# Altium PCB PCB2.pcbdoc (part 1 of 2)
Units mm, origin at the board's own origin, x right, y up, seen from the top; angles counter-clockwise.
Board outline 201.42 x 135 mm, 2 copper layers (Top Layer, Bottom Layer); 117 components, 69 nets, 446 pads, 480 vias.
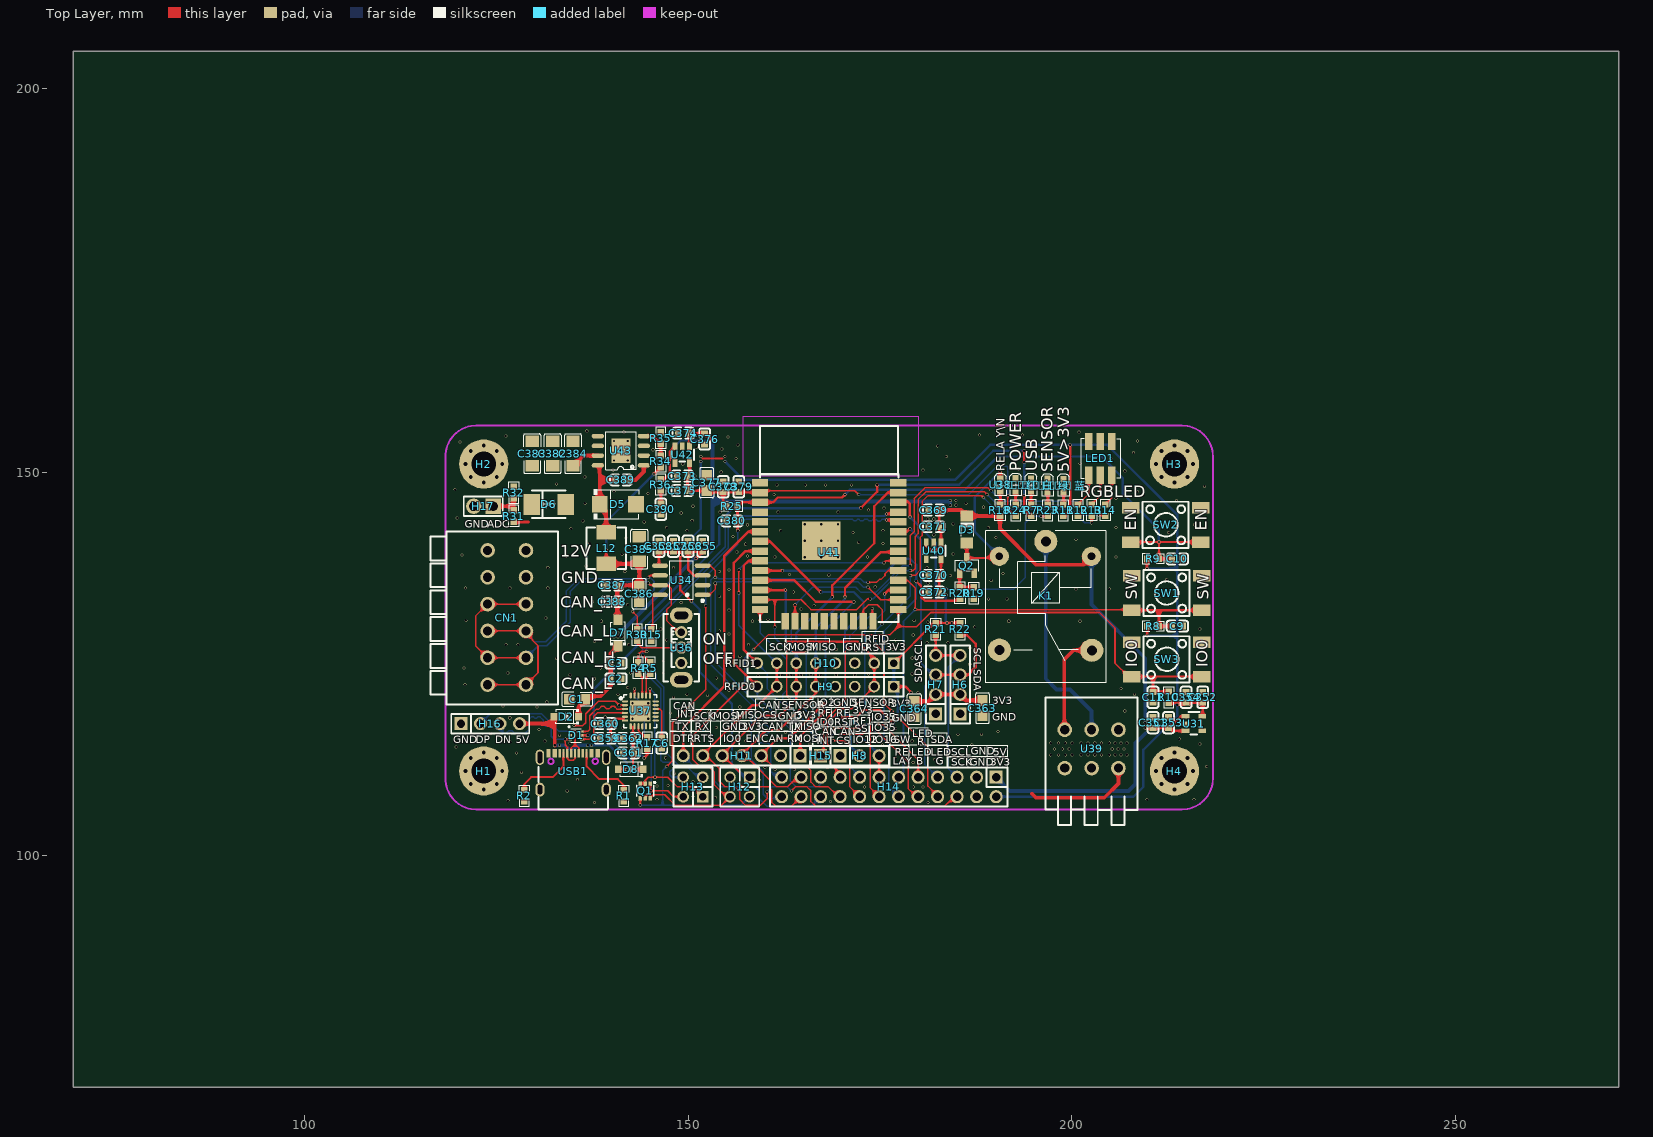
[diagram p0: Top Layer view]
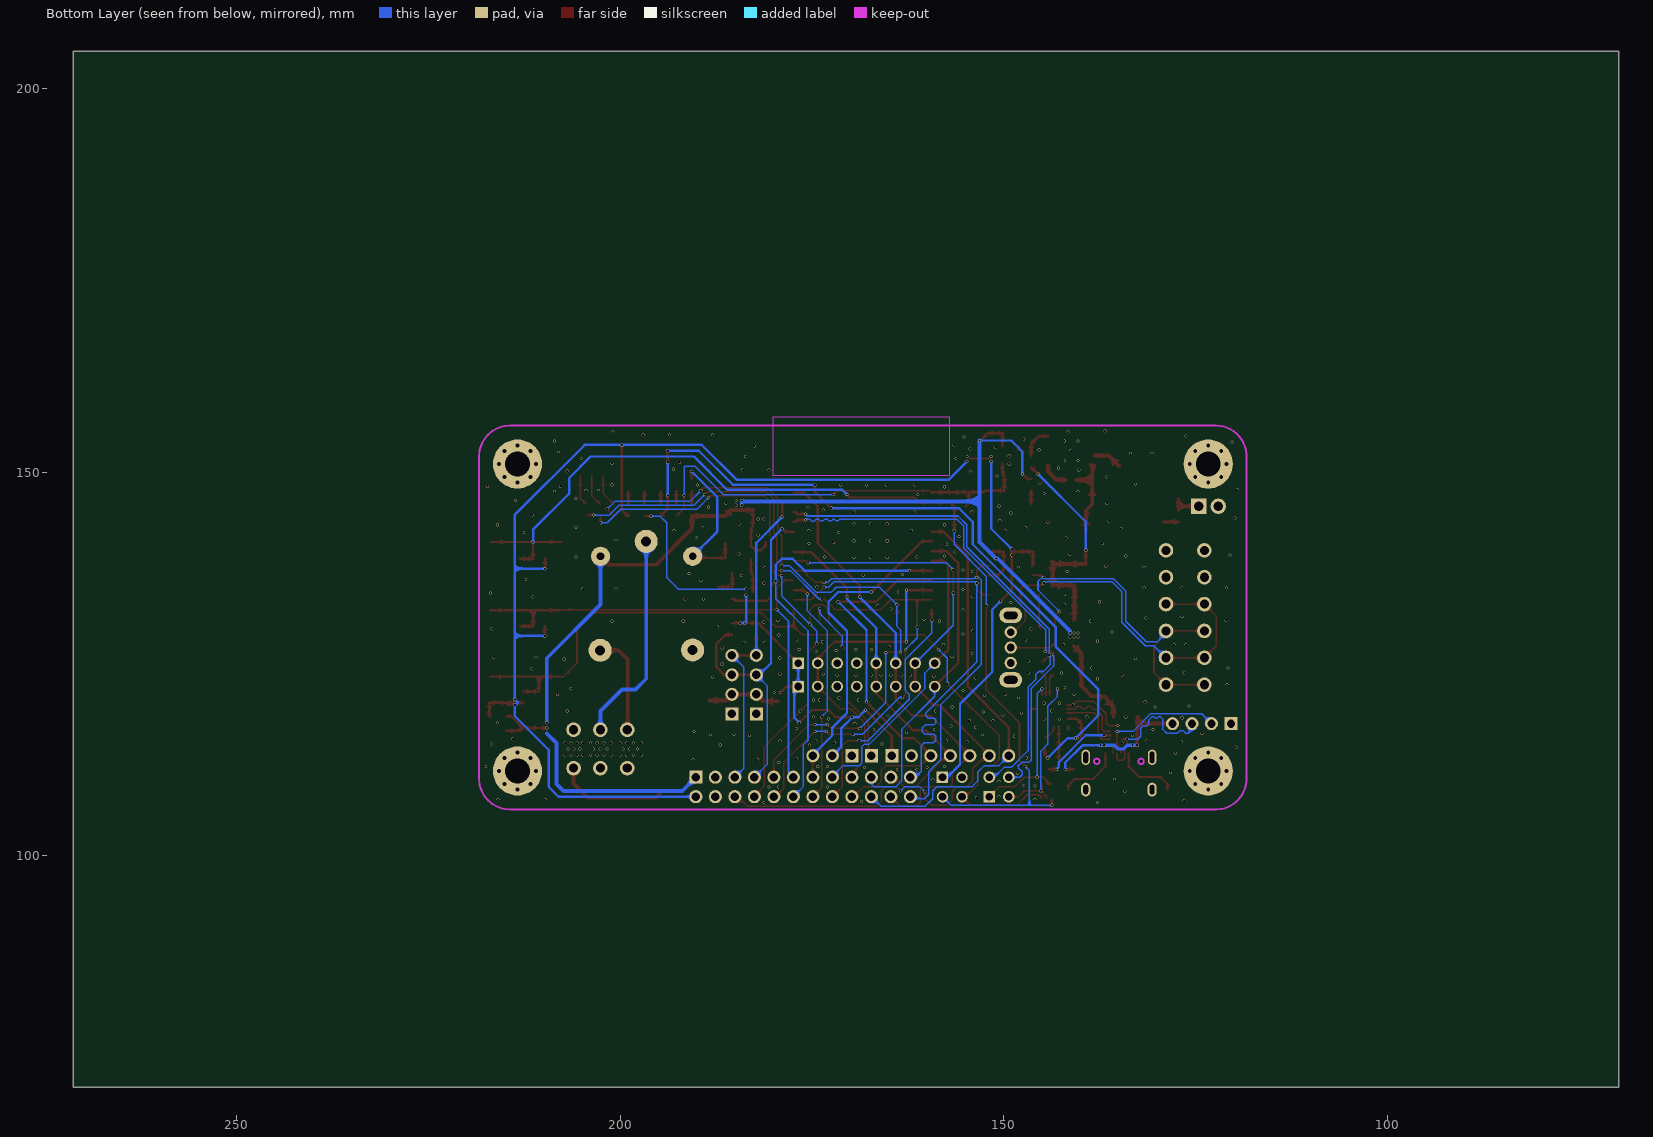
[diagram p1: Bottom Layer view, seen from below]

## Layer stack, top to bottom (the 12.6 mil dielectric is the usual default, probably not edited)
Top Layer: signal copper (thickness not stored)
Dielectric: dielectric 0.32, FR-4, Dk 4.8
Bottom Layer: signal copper (thickness not stored)

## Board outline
271.272,69.85 69.85,69.85 69.85,204.851 271.272,204.851

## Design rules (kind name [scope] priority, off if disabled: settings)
Clearance copperThickness1oz [All] p1: gap=0.178 ignorepadtopadclearanceinfootprint=FALSE except(0.099: Track-Track Track-SMDPad SMDPad-SMDPad Track-THPad SMDPad-THPad THPad-THPad Track-Via SMDPad-Via THPad-Via Via-Via Track-Fill SMDPad-Fill THPad-Fill Via-Fill Fill-Fill Track-Region SMDPad-Region THPad-Region Via-Region Fill-Region Region-Region Track-Poly SMDPad-Poly THPad-Poly Via-Poly Fill-Poly Region-Poly Poly-Poly Track-Text SMDPad-Text THPad-Text Via-Text Fill-Text Region-Text Poly-Text Text-Text Track-Hole SMDPad-Hole THPad-Hole Via-Hole Fill-Hole Region-Hole Poly-Hole Text-Hole; 0.254: SMDPad-Sheet; 0.3: Track-Sheet THPad-Sheet Via-Sheet Fill-Sheet Region-Sheet Poly-Sheet Text-Sheet Sheet-Hole)
Clearance copperThickness2oz [All] p1: gap=0.178 ignorepadtopadclearanceinfootprint=FALSE except(0.152: Track-SMDPad SMDPad-SMDPad Track-THPad SMDPad-THPad THPad-THPad Track-Via SMDPad-Via THPad-Via Via-Via Track-Fill SMDPad-Fill THPad-Fill Via-Fill Fill-Fill SMDPad-Region THPad-Region Via-Region Fill-Region Region-Region Track-Poly SMDPad-Poly THPad-Poly Via-Poly Fill-Poly Poly-Poly Track-Text SMDPad-Text THPad-Text Via-Text Fill-Text Region-Text Poly-Text Text-Text Track-Hole SMDPad-Hole THPad-Hole Via-Hole Fill-Hole Region-Hole Poly-Hole Text-Hole; 0.203: Track-Track; 0.3: Track-Region Region-Poly Track-Sheet SMDPad-Sheet THPad-Sheet Via-Sheet Fill-Sheet Region-Sheet Poly-Sheet Text-Sheet Sheet-Hole)
Clearance copperThicknessInner0.5oz [All] p1: gap=0.178 ignorepadtopadclearanceinfootprint=FALSE except(0.089: Track-Track; 0.152: Track-SMDPad SMDPad-SMDPad Track-THPad SMDPad-THPad THPad-THPad Track-Via SMDPad-Via THPad-Via Via-Via Track-Fill SMDPad-Fill THPad-Fill Via-Fill Fill-Fill SMDPad-Region THPad-Region Via-Region Fill-Region Region-Region Track-Poly SMDPad-Poly THPad-Poly Via-Poly Fill-Poly Poly-Poly Track-Text SMDPad-Text THPad-Text Via-Text Fill-Text Region-Text Poly-Text Text-Text Track-Hole SMDPad-Hole THPad-Hole Via-Hole Fill-Hole Region-Hole Poly-Hole Text-Hole; 0.3: Track-Region Region-Poly Track-Sheet SMDPad-Sheet THPad-Sheet Via-Sheet Fill-Sheet Region-Sheet Poly-Sheet Text-Sheet Sheet-Hole)
DiffPairsRouting differentialPair [All] p1: maxuncoupledlength=10 maxlimit=7.874 mostfreqgap=7.874 toplayer_minwidth=5 toplayer_prefwidth=10 toplayer_maxwidth=100 bottomlayer_minwidth=5 bottomlayer_prefwidth=10 bottomlayer_maxwidth=100
PasteMaskExpansion pasteMaskExpansion [All] p1:
PlaneConnect innerPlane [All] p1: planeconnectstyle=Relief reliefexpansion=0.508 reliefentries=4 reliefconductorwidth=0.254 reliefairgap=0.254
PolygonConnect copperRegionvusb [All] p1: connectstyle=Direct reliefentries=4 reliefconductorwidth=10 polygonreliefangle="90 Angle" airgapwidth=10
PolygonConnect copperRegion0p2 [All] p1: connectstyle=Direct reliefentries=4 reliefconductorwidth=10 polygonreliefangle="90 Angle" airgapwidth=10
PolygonConnect copperRegion1 [All] p1: connectstyle=Direct reliefentries=4 reliefconductorwidth=10 polygonreliefangle="90 Angle" airgapwidth=10
RoutingVias viaSize [All] p1: viastyle="Through Hole" holewidth=11.811 minholewidth=11.811 maxholewidth=248.0314 width=15.748 minwidth=15.748 maxwidth=393.7008
SolderMaskExpansion solderMaskExpansion [All] p1: useseparateexpansions=TRUE expansion=2.0079 expansionbottom=2.0079
Width copperThickness1oz [All] p1: maxlimit=394 minlimit=4 preferedwidth=8
Width copperThickness0.5oz [All] p1: maxlimit=100 minlimit=4 preferedwidth=10
Width copperThickness2oz [All] p1: maxlimit=100 minlimit=8 preferedwidth=10

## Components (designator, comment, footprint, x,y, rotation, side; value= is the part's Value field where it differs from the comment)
C1 "CGA0805X5R226M350MT" C0805 135.509,120.396 r180 top
C2 "CL10A106MA8NRNC" C0603 140.589,123.063 r0 top
C3 "CGA0603X7R104K500JT" C0603 140.589,125.095 r0 top
C6 "CGA0603X5R475K250JT" C0603 146.558,114.681 r90 top
C9 "CGA0603X7R104K500JT" C0603 213.741,129.921 r0 top
C10 "CGA0603X7R104K500JT" C0603 213.741,138.684 r0 top
C11 "CGA0603X7R104K500JT" C0603 210.566,120.65 r270 top
C351 "CL10A106MA8NRNC" C0603 210.566,117.348 r270 top
C352 "CL10A106MA8NRNC" C0603 217.043,120.65 r270 top
C353 "CGA0603X7R104K500JT" C0603 212.598,117.348 r270 top
C354 "CGA0603X7R104K500JT" C0603 214.884,120.65 r270 top
C355 "CL10A106MA8NRNC" C0603 151.892,140.335 r270 top
C356 "CGA0603X7R104K500JT" C0603 149.987,140.335 r270 top
C357 "CL10A106MA8NRNC" C0603 148.082,140.335 r270 top
C358 "CGA0603X7R104K500JT" C0603 146.177,140.335 r270 top
C359 "CGA0603X7R104K500JT" C0603 139.192,115.316 r0 top
C360 "CGA0603X5R475K250JT" C0603 139.192,117.221 r0 top
C361 "CL10A106MA8NRNC" C0603 142.24,113.411 r0 top
C362 "CGA0603X7R104K500JT" C0603 142.24,115.316 r0 top
C363 "CGA0805X5R226M350MT" C0805 188.341,119.253 r270 top
C364 "CGA0805X5R226M350MT" C0805 179.451,119.126 r270 top
C369 "CL10A106MA8NRNC" C0603 181.991,145.034 r0 top
C370 "CL10A106MA8NRNC" C0603 181.991,136.525 r0 top
C371 "CGA0603X7R104K500JT" C0603 181.991,142.875 r0 top
C372 "CGA0603X7R104K500JT" C0603 181.991,134.366 r0 top
C373 "CL10A106MA8NRNC" C0603 149.225,149.479 r0 top
C374 "CGA0603X7R104K500JT" C0603 149.352,155.067 r0 top
C375 "CGA0603X7R104K500JT" C0603 149.225,147.574 r0 top
C376 "CL10A106MA8NRNC" C0603 152.146,154.305 r90 top
C377 "CGA0805X5R226M350MT" C0805 152.4,148.59 r90 top
C378 "CL10A106MA8NRNC" C0603 154.559,148.082 r90 top
C379 "CGA0603X7R104K500JT" C0603 156.591,148.082 r90 top
C380 "CGA0603X7R104K500JT" C0603 155.702,143.637 r180 top
C382 "HGC1206R5106K500NSPJ" C1206 132.334,152.4 r270 top
C383 "CGA1206X5R226M350NT" C1206 129.667,152.4 r270 top
C384 "CL31B104KBCNNNC" C1206 135.001,152.4 r270 top
C385 "HGC1206R5476M250NSPJ" C1206 143.637,139.954 r270 top
C386 "CGA0805X5R226M350MT" C0805 143.637,134.112 r90 top
C387 "CL10A106MA8NRNC" C0603 140.081,135.255 r0 top
C388 "CGA0603X7R104K500JT" C0603 140.081,133.096 r0 top
C389 "CGA0603X7R104K500JT" C0603 141.224,148.971 r0 top
C390 "CGA0603X5R475K250JT" C0603 146.431,145.161 r90 top
CN1 "New_Library_2601-1106" CONN-TH_2601-1106 126.364,131.045 r270 top
D1 "USBLC6-2P6_C2827693" SOT-666-6_L1.6-W1.2-P0.50-LS1.6-BL 135.382,115.697 r270 top
D2 "5819W" SOD-123_L2.7-W1.6-LS3.7-FD 134.112,118.11 r0 top
D3 "LL4148-GS08" SOD-80_L3.5-W1.5-RD 186.309,142.494 r270 top
D5 "SS54SMB" SMB_L4.6-W3.6-LS5.3-RD 140.843,145.796 r0 top
D6 "SMBJ28A" SMB_L4.6-W3.6-LS5.3-L-FD 131.826,145.796 r180 top
D7 "DSK34_C7502709" SOD-123FL_L2.7-W1.8-LS3.8-RD 140.843,129.032 r90 top
D8 "5819W" SOD-123_L2.7-W1.6-LS3.7-FD 142.494,111.252 r0 top
H1 "Mechanical_MountingHole_Pad" MountingHole:MountingHole_3.2mm_M3_Pad_Via 123.364,111.045 r0 top
H2 "Mechanical_MountingHole_Pad" MountingHole:MountingHole_3.2mm_M3_Pad_Via 123.364,151.045 r0 top
H3 "Mechanical_MountingHole_Pad" MountingHole:MountingHole_3.2mm_M3_Pad_Via 213.364,151.045 r0 top
H4 "Mechanical_MountingHole_Pad" MountingHole:MountingHole_3.2mm_M3_Pad_Via 213.364,111.045 r0 top
H6 "PZ254V-11-04P" HDR-TH_4P-P2.54-V-M 185.42,122.301 r90 top
H7 "PZ254V-11-04P" HDR-TH_4P-P2.54-V-M 182.245,122.301 r90 top
H8 "PZ254V-11-03P" HDR-TH_3P-P2.54-V-M 172.339,113.03 r0 top
H9 "PZ254V-11-08P" HDR-TH_8P-P2.54-V-M 167.894,122.047 r180 top
H10 "PZ254V-11-08P" HDR-TH_8P-P2.54-V-M 167.894,125.095 r180 top
H11 "HX PZ2.54-1x7P ZZ" HDR-TH_7P-P2.54-V-M 156.972,113.03 r180 top
H12 "HX PZ2.54-2x2P ZZ" HDR-TH_HX-PZ2.54-2X2P-ZZ 156.718,108.966 r180 top
H13 "HX PZ2.54-2x2P ZZ" HDR-TH_HX-PZ2.54-2X2P-ZZ 150.622,108.966 r90 top
H14 "PZ254V-12-24P" HDR-TH_24P-P2.54-V-M-R2-C12-S2.54 176.149,108.966 r180 top
H15 "PZ254V-11-01P" HDR-TH_1P-P2.54-V-M 167.259,113.03 r0 top
H16 "PZ254V-11-04P" HDR-TH_4P-P2.54-V-M 124.206,117.221 r0 top
H17 "PZ254V-11-02P" HDR-TH_2P-P2.54-V-M 123.317,145.542 r180 top
K1 "Relay_SANYOU_SRD_Form_C" Relay_THT:Relay_SPDT_SANYOU_SRD_Series_Form_C 196.596,140.97 r270 top
L12 "FXL0530-100-M" IND-SMD_L5.4-W5.2_FXL0530 139.319,140.081 r270 top
LED1 "TC5050RGBF08-3CJH-AF53A" LED-SMD_6P-L5.0-W5.0-TL_TC5050RGBF08 203.708,151.765 r90 top
LED白 "NCD0603W1" LED0603-RD 194.691,148.209 r270 top
LED红 "SZYY0603R" LED0603-R-RD 192.659,148.336 r270 top
LED绿 "XL-1608PGC-06" LED0603-RD_GREEN 196.85,148.209 r270 top
LED蓝 "SZYY0603B" LED0603-R-RD_BLUE 198.882,148.209 r270 top
Q1 "UMH3N" SC-70-6_L2.2-W1.3-P0.65-LS2.1-BR 144.399,108.458 r90 top
Q2 "BC817_C916383" SOT-23-3_L2.9-W1.3-P1.90-LS2.4-BR 186.309,137.795 r270 top
R1 "0603WAF5101T5E" R0603 141.605,107.823 r270 top
R2 "0603WAF5101T5E" R0603 128.651,107.823 r270 top
R4 "0603WAF220JT5E" R0603 143.51,124.46 r90 top
R5 "0603WAF220JT5E" R0603 145.034,124.46 r90 top
R7 "0603WAF1002T5E" R0603 194.691,145.034 r90 top
R8 "0603WAF1002T5E" R0603 210.566,129.921 r180 top
R9 "0603WAF1002T5E" R0603 210.566,138.684 r180 top
R10 "0603WAF1002T5E" R0603 212.598,120.65 r270 top
R11 "0603WAF1002T5E" R0603 198.882,145.034 r270 top
R12 "0603WAF1001T5E" R0603 200.787,145.034 r90 top
R13 "0603WAF1001T5E" R0603 202.565,145.034 r90 top
R14 "0603WAF1001T5E" R0603 204.343,145.034 r90 top
R15 "0603WAF0000T5E" R0603 145.161,128.778 r270 top
R17 "0603WAF4701T5E" R0603 144.653,114.681 r90 top
R18 "0603WAF1002T5E" R0603 190.627,145.034 r90 top
R19 "0603WAF1002T5E" R0603 187.198,134.239 r270 top
R20 "0603WAF1001T5E" R0603 185.42,134.239 r90 top
R21 "0603WAF4701T5E" R0603 182.245,129.54 r270 top
R22 "0603WAF4701T5E" R0603 185.42,129.54 r270 top
R23 "0603WAF1002T5E" R0603 196.85,145.034 r270 top
R24 "0603WAF1002T5E" R0603 192.659,145.034 r270 top
R25 "0603WAF1002T5E" R0603 155.702,145.542 r0 top
R30 "0603WAF1200T5E" R0603 143.383,128.778 r90 top
R31 "FRC0603F8202TS" R0603 127.254,144.272 r90 top
R32 "0603WAF1002T5E" R0603 127.254,147.32 r270 top
R34 "0603WAF1003T5E" R0603 146.431,151.384 r90 top
R35 "0603WAF3132T5E" R0603 146.431,154.432 r90 top
R36 "FRC0603F4703TS" R0603 146.431,148.336 r90 top
SW1 "KH-6X6X5H-STM" SW-SMD_4P-L6.0-W6.0-P4.50-LS9.0_H5.0 212.344,134.239 r0 top
SW2 "KH-6X6X5H-STM" SW-SMD_4P-L6.0-W6.0-P4.50-LS9.0_H5.0 212.217,143.129 r0 top
SW3 "KH-6X6X5H-STM" SW-SMD_4P-L6.0-W6.0-P4.50-LS9.0_H5.0 212.344,125.603 r0 top
U31 "ME6211C30M5G-N" SOT-23-5_L2.9-W1.6-P0.95-LS2.8-BL 215.9,117.221 r270 top
U34 "TJA1051T/3/1J" SOIC-8_L4.9-W3.9-P1.27-LS6.0-BL 149.098,135.89 r90 top
U36 "HX SS12D07VG5" SW-TH_SS12D07VG3 149.098,127.127 r270 top
U37 "CP2104-F03-GMR" QFN-24_L4.0-W4.0-P0.50-BL-EP2.7 143.764,118.872 r270 top
U38 "MHT192WDT-GOLD" LED0603-RD-YELLOW 190.627,148.209 r270 top
U39 "2601-1103" CONN-TH_6P-P3.50_2601-1103 202.565,113.919 r0 top
U40 "ME6211C30M5G-N" SOT-23-5_L2.9-W1.6-P0.95-LS2.8-BL 181.991,139.73 r180 top
U41 "ESP32-WROOM-32D-N4" WIFIM-SMD_39P-L25.5-W18.0-P1.27-BL 168.364,139.573 r270 top
U42 "ME6211C30M5G-N" SOT-23-5_L2.9-W1.6-P0.95-LS2.8-BL 149.225,152.273 r180 top
U43 "TPS5450MDDAREP" POWERPAD-SO-8_L4.9-W3.9-P1.27-LS6.0-BL-EP 141.224,152.781 r90 top
USB1 "TYPE-C 16PIN 2MD(073)" USB-C-SMD_TYPE-C-6PIN-2MD-073 135.001,110.998 r0 top

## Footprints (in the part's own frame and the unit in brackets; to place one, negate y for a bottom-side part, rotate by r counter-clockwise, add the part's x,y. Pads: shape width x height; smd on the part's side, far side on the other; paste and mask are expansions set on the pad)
C0603 [mm]
  rect 0.8x0.9 smd: 1(-0.7,0) 2(0.7,0)
  silkscreen extent -1.39,-0.71 1.39,0.71
C0805 [mm]
  rect 1.41x1.35 smd: 1(-1,0) 2(1,0)
  silkscreen extent -1.96,-0.9 1.96,0.9
C1206 [mm]
  rect 1.485x1.728 smd: 1(-1.593,0) 2(1.593,0)
  silkscreen extent -2.56,-1.09 2.56,1.09
CONN-TH_6P-P3.50_2601-1103 [mm]
  round 1.9 hole 1.2: 1(-3.5,2.5) 2(-3.5,-2.5) 3(0,2.5) 4(0,-2.5) 5(3.5,2.5) 6(3.5,-2.5)
  silkscreen extent -6,-9.9 6,6.7
CONN-TH_2601-1106 [mm]
  round 1.9 hole 1.2: 1(-8.75,-2.5) 1(-8.75,2.5) 2(-5.25,2.5) 2(-5.25,-2.5) 3(-1.75,2.5) 3(-1.75,-2.5) 4(1.75,2.5) 4(1.75,-2.5) 5(5.25,2.5) 5(5.25,-2.5) 6(8.75,-2.5) 6(8.75,2.5)
  silkscreen extent -11.19,-9.93 11.31,6.65
HDR-TH_1P-P2.54-V-M [mm]
  rect 1.7x1.7 hole 1.1: 1(0,0)
  silkscreen extent -1.27,-1.27 1.27,1.27
HDR-TH_2P-P2.54-V-M [mm]
  rect 2x2 hole 1.2: 1(-1.27,0)
  round 2 hole 1.2: 2(1.27,0)
  silkscreen extent -2.54,-1.27 2.54,1.27
HDR-TH_3P-P2.54-V-M [mm]
  rect 1.7x1.7 hole 1.1: 1(-2.54,0)
  round 1.7 hole 1.1: 2(0,0) 3(2.54,0)
  silkscreen extent -3.81,-1.25 3.81,1.25
HDR-TH_4P-P2.54-V-M [mm]
  rect 1.7x1.7 hole 1.1: 1(-3.81,0)
  round 1.7 hole 1.1: 2(-1.27,0) 3(1.27,0) 4(3.81,0)
  silkscreen extent -5.08,-1.27 5.08,1.27
HDR-TH_7P-P2.54-V-M [mm]
  rect 1.7x1.7 hole 1.1: 1(-7.62,0)
  round 1.7 hole 1.1: 2(-5.08,0) 3(-2.54,0) 4(0,0) 5(2.54,0) 6(5.08,0) 7(7.62,0)
  silkscreen extent -8.89,-1.25 8.89,1.25
HDR-TH_8P-P2.54-V-M [mm]
  rect 1.5x1.5 hole 1: 1(-8.89,0)
  round 1.5 hole 1: 2(-6.35,0) 3(-3.81,0) 4(-1.27,0) 5(1.27,0) 6(3.81,0) 7(6.35,0) 8(8.89,0)
  silkscreen extent -10.16,-1.27 10.16,1.27
HDR-TH_24P-P2.54-V-M-R2-C12-S2.54 [mm]
  rect 1.7x1.7 hole 1.1: 1(-13.97,-1.27)
  round 1.7 hole 1.1: 2(-13.97,1.27) 3(-11.43,-1.27) 4(-11.43,1.27) 5(-8.89,-1.27) 6(-8.89,1.27) 7(-6.35,-1.27) 8(-6.35,1.27) 9(-3.81,-1.27) 10(-3.81,1.27) 11(-1.27,-1.27) 12(-1.27,1.27) 13(1.27,-1.27) 14(1.27,1.27) 15(3.81,-1.27) 16(3.81,1.27) 17(6.35,-1.27) 18(6.35,1.27) 19(8.89,-1.27) 20(8.89,1.27) 21(11.43,-1.27) 22(11.43,1.27) 23(13.97,-1.27) 24(13.97,1.27)
  silkscreen extent -15.47,-2.54 15.47,2.54
HDR-TH_HX-PZ2.54-2X2P-ZZ [mm]
  rect 1.5x1.5 hole 1.02: 1(-1.27,-1.27)
  round 1.5 hole 1.02: 2(-1.27,1.27) 3(1.27,-1.27) 4(1.27,1.27)
  silkscreen extent -2.54,-2.54 2.54,2.54
IND-SMD_L5.4-W5.2_FXL0530 [mm]
  rect 1.9x2.5 smd: 1(-2.05,0) 2(2.05,0)
  silkscreen extent -2.7,-2.6 2.7,2.6
LED0603-R-RD [mm]
  rect 0.8x0.8 smd: 1(0.851,0) 2(-0.851,0)
  silkscreen extent -1.44,-0.75 1.44,0.75
LED0603-R-RD_BLUE [mm]
  rect 0.8x0.8 smd: 1(0.8,0.038) 2(-0.902,0.038)
  silkscreen extent -1.49,-0.71 1.39,0.79
LED0603-RD [mm]
  rect 0.8x0.8 smd: 1(-0.963,-0.005) 2(0.739,-0.005)
  silkscreen extent -1.55,-0.76 1.33,0.75
LED0603-RD-YELLOW [mm]
  rect 0.8x0.8 smd: 1(-0.965,0.038) 2(0.737,0.038)
  silkscreen extent -1.55,-0.71 1.33,0.79
LED0603-RD_GREEN [mm]
  rect 0.8x0.8 smd: 1(-0.911,-0.05) 2(0.791,-0.05)
  silkscreen extent -1.5,-0.8 1.38,0.7
LED-SMD_6P-L5.0-W5.0-TL_TC5050RGBF08 [mm]
  rect 2.265x1 smd: 1(-2.208,1.5) 2(-2.208,0) 3(-2.208,-1.5) 4(2.208,-1.5) 5(2.208,0) 6(2.208,1.5)
  silkscreen extent -3.81,-2.58 2.58,2.58
MountingHole:MountingHole_3.2mm_M3_Pad_Via [mm]
  round 0.8 hole 0.5: 1(-2.4,0) 1(-1.697,-1.697) 1(-1.697,1.697) 1(0,-2.4) 1(0,2.4) 1(1.697,-1.697) 1(1.697,1.697) 1(2.4,0)
  round 6.4 hole 3.2: 1(0,0)
POWERPAD-SO-8_L4.9-W3.9-P1.27-LS6.0-BL-EP [mm]
  oval 0.6x1.6 smd: 1(-1.905,-3) 2(-0.635,-3) 3(0.635,-3) 4(1.905,-3) 5(1.905,3) 6(0.635,3) 7(-0.635,3) 8(-1.905,3)
  rect 3.2x2.5 smd: 9(0,0)
  silkscreen extent -2.5,-2 2.5,2
QFN-24_L4.0-W4.0-P0.50-BL-EP2.7 [mm]
  oval 0.28x0.8 smd: 1(-1.25,-2) 2(-0.75,-2) 3(-0.25,-2) 4(0.25,-2) 5(0.75,-2) 6(1.25,-2) 13(1.25,2) 14(0.75,2) 15(0.25,2) 16(-0.25,2) 17(-0.75,2) 18(-1.242,2)
  oval 0.8x0.28 smd: 7(2,-1.25) 8(2,-0.75) 9(2,-0.25) 10(2,0.25) 11(2,0.75) 12(2,1.25) 19(-2,1.25) 20(-2,0.75) 21(-2,0.25) 22(-2,-0.25) 23(-2,-0.75) 24(-2,-1.25)
  rect 2.7x2.7 smd: 25(0.012,0)
  silkscreen extent -2.14,-2.79 2.16,2.15
R0603 [mm]
  rect 0.806x0.864 smd: 1(-0.753,0) 2(0.753,0)
  silkscreen extent -1.39,-0.66 1.39,0.66
Relay_THT:Relay_SPDT_SANYOU_SRD_Series_Form_C [mm]
  round 3 hole 1.3: 1(0,0) 3(14.15,-6.05) 4(14.2,6)
  round 2.5 hole 1: 2(1.95,-6.05) 5(1.95,5.95)
  silkscreen extent -1.4,-7.8 18.4,7.8
SC-70-6_L2.2-W1.3-P0.65-LS2.1-BR [mm]
  rect 0.6x0.42 smd: 1(0.95,-0.65) 2(0.95,0) 3(0.95,0.65) 4(-0.95,0.65) 5(-0.95,0) 6(-0.95,-0.65)
  silkscreen extent -0.7,-1.34 1.22,1.1
SMB_L4.6-W3.6-LS5.3-L-FD [mil]
  rect 85x108 smd: 1(-87,0) 2(87,0)
  silkscreen extent -85,-70 85,70
SMB_L4.6-W3.6-LS5.3-RD [mm]
  rect 2.047x2.192 smd: 1(-2.361,0) 2(2.361,0)
  silkscreen extent -3.12,-1.96 2.74,1.96
SOD-80_L3.5-W1.5-RD [mm]
  rect 1.44x1.62 smd: 1(-1.765,0) 2(1.765,0)
  silkscreen extent -0.84,-0.83 0.84,0.83
SOD-123_L2.7-W1.6-LS3.7-FD [mm]
  rect 0.88x0.96 smd: 1(-1.61,0) 2(1.61,0)
  silkscreen extent -1.38,-1 1.6,1
SOD-123FL_L2.7-W1.8-LS3.8-RD [mm]
  rect 1.4x1.2 smd: 1(-1.735,0) 2(1.735,0)
  silkscreen extent -1.6,-1 1.38,1
SOIC-8_L4.9-W3.9-P1.27-LS6.0-BL [mm]
  oval 0.588x2.045 smd: 1(-1.905,-2.772) 2(-0.635,-2.772) 3(0.635,-2.772) 4(1.905,-2.772) 5(1.905,2.772) 6(0.635,2.772) 7(-0.635,2.772) 8(-1.905,2.772)
  silkscreen extent -2.8,-2.92 2.53,1.52
SOT-23-3_L2.9-W1.3-P1.90-LS2.4-BR [mm]
  rect 1.25x0.7 smd: 1(1,-0.95) 2(1,0.95) 3(-1,0)
  silkscreen extent -0.73,-1.53 0.73,1.53
SOT-23-5_L2.9-W1.6-P0.95-LS2.8-BL [mm]
  rect 0.6x1 smd: 1(-0.95,-1.1) 2(0,-1.1) 3(0.95,-1.1) 4(0.95,1.1) 5(-0.95,1.1)
  silkscreen extent -1.52,-0.7 1.4,0.89
SOT-666-6_L1.6-W1.2-P0.50-LS1.6-BL [mm]
  rect 0.3x0.5 smd: 1(-0.5,-0.75) 2(0,-0.75) 3(0.5,-0.75) 4(0.5,0.75) 5(0,0.75) 6(-0.5,0.75)
  silkscreen extent -1.21,-1.01 0.88,0.68
SW-SMD_4P-L6.0-W6.0-P4.50-LS9.0_H5.0 [mm]
  rect 2.3x1.5 smd: 1(-4.55,2.25) 2(4.55,2.25) 3(-4.55,-2.25) 4(4.55,-2.25)
  silkscreen extent -3,-3 3,3
SW-TH_SS12D07VG3 [mm]
  round 1.6 hole 1: 1(-2,0) 2(0,0) 3(2,0)
  oval 2x3 hole 1 slot 1.8 at 90 deg: 4(4.2,0) 5(-4.2,0)
  silkscreen extent -4.4,-2.3 4.4,2.3
USB-C-SMD_TYPE-C-6PIN-2MD-073 [mm]
  rect 0.55x1.1 smd: 1(-3.2,2.375) 2(-2.4,2.375) 11(2.4,2.375) 12(3.2,2.375)
  rect 0.3x1.1 smd: 3(-1.75,2.375) 4(-1.25,2.375) 5(-0.75,2.375) 6(-0.25,2.375) 7(0.25,2.375) 8(0.75,2.375) 9(1.25,2.375) 10(1.75,2.375)
  oval 1.1x2 hole 0.6 slot 1.5 at 90 deg: 13(-4.325,1.825) 14(4.325,1.825)
  oval 1.2x1.8 hole 0.6 slot 1.2 at 90 deg: 13(-4.325,-2.375) 14(4.325,-2.375)
  Multi-Layer board cut-out: -2.54,1.305 -2.589,1.477 -2.717,1.603 -2.89,1.648 -3.063,1.603 -3.191,1.477 -3.24,1.305 -3.24,1.305 -3.191,1.133 -3.063,1.007 -2.89,0.962 -2.717,1.007 -2.589,1.133 -2.54,1.305
  Multi-Layer board cut-out: 3.24,1.305 3.206,1.457 3.108,1.579 2.968,1.646 2.812,1.646 2.672,1.579 2.575,1.457 2.54,1.305 2.54,1.305 2.575,1.153 2.672,1.031 2.812,0.964 2.968,0.964 3.108,1.031 3.205,1.153 3.24,1.305
  Multi-Layer keep-out circle w0.254: c-2.89,1.305 r0.35
  Multi-Layer keep-out circle w0.254: c2.89,1.305 r0.35
  silkscreen extent -4.5,-4.97 4.57,0.6
WIFIM-SMD_39P-L25.5-W18.0-P1.27-BL [mm]
  rect 0.95x2.1 smd: 1(-9.015,-9) 2(-7.745,-9) 3(-6.475,-9) 4(-5.205,-9) 5(-3.935,-9) 6(-2.665,-9) 7(-1.395,-9) 8(-0.125,-9) 9(1.145,-9) 10(2.415,-9) 11(3.685,-9) 12(4.955,-9) 13(6.225,-9) 14(7.495,-9) 25(7.495,9) 26(6.225,9) 27(4.955,9) 28(3.685,9) 29(2.415,9) 30(1.145,9) 31(-0.125,9) 32(-1.395,9) 33(-2.665,9) 34(-3.935,9) 35(-5.205,9) 36(-6.475,9) 37(-7.745,9) 38(-9.015,9)
  rect 2.1x0.95 smd: 15(9.015,-5.715) 16(9.015,-4.445) 17(9.015,-3.175) 18(9.015,-1.905) 19(9.015,-0.635) 20(9.015,0.635) 21(9.015,1.905) 22(9.015,3.175) 23(9.015,4.445) 24(9.015,5.715)
  rect 5x5 smd: 39(-1.472,-1.017)
  silkscreen extent -16.44,-9.02 9.12,9.02

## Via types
v1: diameter 0.4, hole 0.3, Top Layer to Bottom Layer, 480 vias

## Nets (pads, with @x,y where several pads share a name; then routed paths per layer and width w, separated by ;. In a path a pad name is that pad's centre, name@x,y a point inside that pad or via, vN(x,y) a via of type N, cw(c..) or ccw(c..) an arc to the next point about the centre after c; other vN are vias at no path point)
3.3_SENSOR: C363.1 C364.1 C370.2 C372.2 H6.2 H7.2 H8.2 H9.1 H10.1 H11.1 R21.1 R22.1 R23.2 U40.5 | length 84.9
  Top Layer w0.2: v1(195.961,144.239) 196.808,144.239 R23.2@196.85,144.281
  Top Layer w0.312: H11.1@164.592,113.03 164.592,115.57 v1(168.021,118.999) ; v1(169.736,118.046) 171.894,118.046 172.847,118.999 175.006,118.999 v1(176.657,117.348) ; H9.1@176.784,122.047 178.292,122.047 v1(179.07,121.269) ; H10.1@176.784,125.095 181.982,130.293 R21.1@182.245,130.293 182.287,130.335 v1(183.711,130.335) v1(184.346,130.335) 185.378,130.335 R22.1@185.42,130.293 ; C372.2@182.691,134.366 C370.2@182.691,136.525 182.941,136.775 U40.5@182.941,138.63
  Top Layer w0.5: C364.1@179.451,120.126 181.34,120.126 H7.2@182.245,121.031 H6.2@185.42,121.031 186.198,120.253 C363.1@188.341,120.253
  Bottom Layer w0.2: v1(183.576,134.747) 192.405,134.747 193.929,136.271 193.929,143.383 194.785,144.239 v1(195.961,144.239)
  Bottom Layer w0.312: v1(168.021,118.999) 168.974,118.046 v1(169.736,118.046) 171.196,116.586 171.196,114.173 H8.2@172.339,113.03 ; v1(176.657,117.348) 177.292,117.983 177.292,121.539 H9.1@176.784,122.047 H10.1@176.784,125.095 ; v1(183.576,133.985) 183.576,130.495 183.736,130.335 v1(184.346,130.335)
  other v1: 179.959,121.269
3V3: C352.2 C354.2 C357.2 C358.2 H12.1 H14.2 R8.2 R9.2 R10.2 R11.2 U31.5 U34.5 | length 204.4
  Top Layer w0.312: U34.5@146.326,137.795 146.177,137.944 C358.2@146.177,139.635 C357.2@148.082,139.635 148.652,139.635 v1(148.971,139.954) v1(148.971,139.192) 148.971,134.62 v1(150.431,133.16) ; 151.892,151.765 154.432,151.765 ; R11.2@198.882,144.281 199.018,144.281 199.778,145.041 v1(199.778,153.543) ; v1(209.771,137.414) 209.771,138.642 R9.2@209.813,138.684 ; v1(209.813,128.651) R8.2@209.813,129.921 ; R10.2@212.598,119.897 212.651,119.95 C354.2@214.884,119.95 ; v1(213.741,119.696) 214.63,119.696 C354.2@214.884,119.95 ; U31.5@217,118.171 217.043,118.214 C352.2@217.043,119.95 C354.2@214.884,119.95
  Bottom Layer w0.312: v1(148.971,139.954) 151.638,142.621 v1(151.638,151.384) ; v1(150.431,133.16) 151.511,132.08 151.511,123.952 155.702,119.761 155.702,111.887 157.353,110.236 H12.1@157.988,110.236 ; v1(154.813,151.384) 157.226,148.971 184.785,148.971 189.357,153.543 v1(199.778,153.543) 204.597,153.543 213.741,144.399 213.741,137.414 ; H14.2@190.119,107.696 208.026,107.696 209.296,108.966 209.296,113.792 213.741,118.237 213.741,119.526 213.317,119.95 v1(213.741,120.374) 213.741,128.697 ; v1(209.771,137.414) 213.741,137.414 ; v1(209.813,128.651) 213.695,128.651 213.741,128.697 ; 213.741,128.697 213.741,137.414
  other v1: 151.638,152.019 154.813,152.019
3V3_POWER: C373.2 C375.2 C377.1 C378.1 C379.1 R24.2 R25.1 U41.2 U42.5 | length 56.2
  Top Layer w0.2: U41.2@159.364,147.318 159.62,147.574 171.704,147.574 v1(172.212,147.066) ; v1(191.643,146.939) 191.643,145.297 R24.2@192.659,144.281
  Top Layer w0.312: U42.5@150.175,151.173 150.175,149.729 C373.2@149.925,149.479 C375.2@149.925,147.574 152.384,147.574 C377.1@152.4,147.59 152.608,147.382 C378.1@154.559,147.382 ; R25.1@154.949,145.542 154.559,145.932 C378.1@154.559,147.382 ; U41.2@159.364,147.318 159.3,147.382 C379.1@156.591,147.382 C378.1@154.559,147.382
  Bottom Layer w0.2: v1(172.212,147.066) 186.563,147.066 190.246,150.749 191.516,150.749 191.643,150.622 v1(191.643,146.939)
$1N379: R1.1 USB1.10 | length 8.2
  Top Layer w0.254: USB1.10@136.751,113.373 136.751,111.661 138.43,109.982 140.843,109.982 141.605,109.22 R1.1@141.605,108.576
$1N383: R2.1 USB1.4 | length 8.5
  Top Layer w0.254: R2.1@128.651,108.576 128.651,109.347 129.54,110.236 132.334,110.236 133.731,111.633 133.731,113.353 USB1.4@133.751,113.373
$1N1005: D1.4 U37.4 | length 8.5
  Top Layer w0.2: D1.4@136.132,115.197 137.168,115.197 137.668,115.697 137.668,118.11 138.18,118.622 U37.4@141.764,118.622
$1N1016: D1.6 U37.3 | length 8.5
  Top Layer w0.2: D1.6@136.132,116.197 136.14,116.205 136.906,116.205 137.16,116.459 137.16,118.237 138.045,119.122 138.369,119.122 138.716,119.469 139.039,119.469 139.376,119.131 139.686,119.131 140.039,119.485 140.355,119.485 140.718,119.122 U37.3@141.764,119.122
$1N2492: LED白.2 R7.2 | length 1.7
  Top Layer w0.312: LED白.2@194.686,147.47 194.691,147.465 R7.2@194.691,145.787
$1N3538: LED蓝.1 R11.1 | length 1.6
  Top Layer w0.312: R11.1@198.882,145.787 198.92,145.825 LED蓝.1@198.92,147.409
$1N6214: R15.1 U34.8 | length 5.4
  Top Layer w0.2: R15.1@145.161,129.531 145.361,129.731 145.361,133.804 145.542,133.985 U34.8@146.326,133.985
$1N6447: R30.1 U36.2 | length 6.3
  Top Layer w0.2: R30.1@143.383,128.025 143.383,127.635 143.891,127.127 U36.2@149.098,127.127
$1N8585: C6.2 U37.16 | length 4.4
  Top Layer w0.2: U37.16@145.764,119.122 145.768,119.126 146.304,119.126 146.558,118.872 C6.2@146.558,115.381
$1N8799: R4.1 U37.21 | length 3
  Top Layer w0.2: R4.1@143.51,123.707 144.014,123.203 U37.21@144.014,120.872
$1N8801: R5.1 U37.20 | length 3.1
  Top Layer w0.2: U37.20@144.514,120.872 144.514,123.187 R5.1@145.034,123.707
$1N8937: R17.2 U37.9 | length 2.1
  Top Layer w0.2: U37.9@143.514,116.872 143.514,116.29 144.37,115.434 R17.2@144.653,115.434
$1N9236: R18.2 U38.2 | length 1.7
  Top Layer w0.312: U38.2@190.665,147.472 190.665,145.876 R18.2@190.754,145.787
$1N9240: D3.2 K1.2 Q2.3 U38.1 | length 20.9
  Top Layer w0.312: D3.2@186.309,140.729 Q2.3@186.309,138.795 190.321,138.795 K1.2@190.546,139.02 ; U38.1@190.665,149.174 v1(190.665,150.063)
  Bottom Layer w0.312: K1.2@190.546,139.02 187.325,142.241 187.325,146.723 v1(190.665,150.063)
$1N9454: Q2.1 R19.1 R20.2 | length 3.6
  Top Layer w0.312: Q2.1@185.359,136.795 185.359,135.053 R20.2@185.42,134.992 R19.1@187.198,134.992
$1N9531: K1.4 U39.1 U39.2 | length 13.3
  Top Layer w0.5: U39.1@199.065,116.419 199.009,116.475 199.009,125.603 200.176,126.77 K1.4@202.596,126.77
  other v1: 197.231,113.157 198.247,113.157 199.136,113.157 200.025,113.157 197.739,113.919 198.755,113.919 199.644,113.919 197.231,114.681 198.247,114.681 199.136,114.681 200.025,114.681
$1N9535: K1.1 U39.3 U39.4 | length 28.1
  Bottom Layer w0.5: K1.1@196.596,140.97 196.596,123.063 197.993,121.666 199.771,121.666 202.565,118.872 U39.3@202.565,116.419
  other v1: 201.197,113.157 202.086,113.157 202.975,113.157 203.864,113.157 201.705,113.919 202.594,113.919 203.483,113.919 201.197,114.681 202.086,114.681 202.975,114.681 203.864,114.681
$1N9540: K1.3 U39.5 U39.6 | length 14.2
  Top Layer w0.5: 194.818,108.077 195.326,107.569 204.216,107.569 206.065,109.418 U39.6@206.065,111.419
  other v1: 204.873,113.157 205.635,113.157 206.397,113.157 207.159,113.157 205.254,113.919 206.016,113.919 206.778,113.919 204.873,114.681 205.635,114.681 206.397,114.681 207.159,114.681
$1N10830: LED绿.2 R23.1 | length 1.7
  Top Layer w0.312: LED绿.2@196.8,147.418 196.85,147.368 R23.1@196.85,145.787
$1N11549: LED红.1 R24.1 | length 1.7
  Top Layer w0.312: R24.1@192.659,145.787 LED红.1@192.659,147.485
$1N13650: C389.1 D5.1 L12.1 U43.8 | length 11.4
  Top Layer w0.5: U43.8@138.224,150.876 138.43,150.876 138.482,150.824 138.482,148.922 ; L12.1@139.319,142.131 139.319,144.959 D5.1@138.482,145.796 138.482,148.922 ; C389.1@140.524,148.971 138.531,148.971 138.482,148.922
$1N13751: C385.2 C386.2 C387.2 C388.2 D7.2 L12.2 R34.1 | length 30.7
  Top Layer w0.312: L12.2@139.319,138.031 v1(139.319,139.807) ; v1(145.542,149.742) R34.1@146.431,150.631
  Top Layer w0.5: L12.2@139.319,138.031 143.307,138.031 C385.2@143.637,138.361 C386.2@143.637,135.112 143.494,135.255 C387.2@140.781,135.255 C388.2@140.781,133.096 140.781,130.829 D7.2@140.843,130.767
  Bottom Layer w0.312: v1(139.319,139.807) 139.319,143.519 v1(145.542,149.742)
$1N13789: C389.2 U43.1 | length 3.6
  Top Layer w0.5: C389.2@141.924,148.971 143.129,148.971 144.224,150.066 U43.1@144.224,150.876
$1N38602: LED1.3 R14.2 | length 4.1
  Top Layer w0.2: R14.2@204.343,145.787 205.208,146.652 LED1.3@205.208,149.557
$1N38604: LED1.1 R12.2 | length 4.4
  Top Layer w0.2: R12.2@200.787,145.787 202.208,147.208 LED1.1@202.208,149.557
$1N38606: LED1.2 R13.2 | length 4.2
  Top Layer w0.2: R13.2@202.565,145.787 203.708,146.93 LED1.2@203.708,149.557
$1N38886: C390.2 R36.1 | length 1.7
  Top Layer w0.312: C390.2@146.431,145.861 R36.1@146.431,147.583
+5V: C1.1 C2.1 C3.1 C351.2 C353.2 C355.2 C356.2 C369.2 C371.2 C374.2 C376.2 D2.2 D3.1 D7.1 H14.1 K1.5 R18.1 R36.2 U31.1 U31.3 U34.3 U40.1 U40.3 U42.1 U42.3 | length 192.2
  Top Layer w0.312: R36.2@146.431,149.089 146.93,149.089 v1(147.574,149.733) 147.574,152.654 148.275,153.355 U42.3@148.275,153.373 ; U42.1@150.175,153.373 150.175,154.944 C374.2@150.052,155.067 152.084,155.067 C376.2@152.146,155.005 153.035,154.116 v1(153.162,154.116) ; v1(151.003,138.728) 151.003,138.746 C355.2@151.892,139.635 C356.2@149.987,139.635 149.987,137.287 150.749,136.525 U34.3@151.87,136.525 ; U40.3@181.041,140.83 181.041,140.396 181.61,139.827 182.372,139.827 182.941,140.396 U40.1@182.941,140.83 182.941,142.625 C371.2@182.691,142.875 C369.2@182.691,145.034 ; v1(209.55,116.648) C351.2@210.566,116.648 C353.2@212.598,116.648 C353.2@212.663,116.648 ; U31.3@214.8,116.271 213.04,116.271 C353.2@212.663,116.648 ; U31.1@214.8,118.171 214.186,118.171 C353.2@212.663,116.648
  Top Layer w0.5: D2.2@135.722,118.11 135.722,119.339 136.509,120.126 C1.1@136.509,120.396 136.89,120.777 138.557,120.777 139.889,122.109 C2.1@139.889,123.063 C3.1@139.889,125.095 139.889,126.343 D7.1@140.843,127.297 ; C369.2@182.691,145.034 185.534,145.034 D3.1@186.309,144.259 186.331,144.281 R18.1@190.627,144.281 190.627,142.621 195.326,137.922 201.448,137.922 K1.5@202.546,139.02
  Bottom Layer w0.312: v1(147.574,149.733) 147.574,152.654 149.036,154.116 v1(153.162,154.116)
  Bottom Layer w0.5: v1(141.351,129.032) 141.351,129.286 150.793,138.728 v1(151.003,138.728) 153.162,140.887 153.162,146.177 ; v1(153.162,154.116) 153.162,146.177 ; v1(184.15,145.669) 184.15,146.177 153.162,146.177 ; H14.1@190.119,110.236 191.897,108.458 207.391,108.458 208.28,109.347 208.28,114.681 209.55,115.951 ; K1.5@202.546,139.02 202.546,132.734 209.55,125.73 v1(209.55,117.348)
  other v1: 140.335,128.524 140.843,128.524 141.351,128.524 140.335,129.032 140.843,129.032 184.912,145.669 184.15,146.304 184.912,146.304
ADC: H17.1 R31.2 R32.2 | length 4.2
  Top Layer w0.4: H17.1@124.587,145.542 127.218,145.542 127.254,145.506 ; R31.2@127.254,145.025 127.254,145.506 ; R32.2@127.254,146.567 127.254,145.506
AUX_CAN_CS: H11.3 H14.18 U41.11 | length 52.6
  Top Layer w0.2: H11.3@159.512,113.157 160.909,111.76 165.354,111.76 165.989,111.125 165.989,109.601 166.624,108.966 168.275,108.966 169.545,107.696 H14.18@169.799,107.696
  Top Layer w0.312: U41.11@159.364,135.888 163.832,135.888 166.624,133.096 v1(171.577,133.096) ; H11.3@159.512,113.157 161.671,115.316 163.195,115.316 v1(167.894,120.015)
  Bottom Layer w0.312: v1(167.894,120.015) 167.894,129.413 v1(171.577,133.096)
AUX_CAN_INT: H11.7 H14.20 U41.6 | length 56.5
  Top Layer w0.312: H11.7@149.352,113.157 149.352,116.713 154.686,122.047 154.686,139.065 157.859,142.238 U41.6@159.364,142.238
  Bottom Layer w0.2: H11.7@149.352,113.03 150.622,111.76 152.527,111.76 153.416,110.871 153.416,109.728 154.178,108.966 158.75,108.966 159.258,108.458 159.258,107.442 160.255,106.445 166.008,106.445 H14.20@167.259,107.696
CAN_H: CN1.3 CN1.5 U34.7 U36.1 | length 51
  Top Layer w0.2: CN1.5@128.864,125.795 CN1.5@123.864,125.795 122.301,127.358 122.301,131.232 CN1.3@123.864,132.795 CN1.3@128.864,132.795 ; v1(144.802,135.509) 145.056,135.255 U34.7@146.326,135.255 147.342,135.255 147.807,134.79 147.807,132.679 147.178,132.051 147.178,130.657 148.709,129.127 U36.1@149.098,129.127
  Bottom Layer w0.2: CN1.5@128.864,125.795 130.45,127.381 131.572,127.381 134.62,130.429 134.62,134.435 135.875,135.69 144.621,135.69 v1(144.802,135.509)
CAN_L: CN1.4 CN1.6 R30.2 U34.6 | length 51
  Top Layer w0.2: CN1.6@123.864,122.295 CN1.6@128.864,122.295 130.429,123.86 130.429,127.381 128.864,128.946 CN1.4@128.864,129.295 CN1.4@123.864,129.295 ; v1(142.747,131.818) 143.382,131.183 R30.2@143.383,129.531 ; v1(144.802,136.271) 145.056,136.525 U34.6@146.326,136.525
  Bottom Layer w0.2: CN1.4@128.864,129.295 128.864,129.012 129.987,127.889 131.445,127.889 134.112,130.556 134.112,134.493 135.709,136.09 144.621,136.09 v1(144.802,136.271) 145.034,136.271 145.542,135.763 145.542,134.614 v1(142.747,131.818)
CAN_RX: H14.24 U34.4 U41.29 | length 61.9
  Top Layer w0.2: U34.4@151.87,137.795 152.908,137.795 153.521,137.182 v1(153.521,136.271) ; v1(173.427,135.634) 174.541,135.634 174.909,136.002 175.126,136.002 175.645,136.521 175.645,136.738 176.065,137.158 U41.29@177.364,137.158
  Bottom Layer w0.2: H14.24@162.179,107.696 161.925,107.442 160.349,107.442 159.766,108.025 159.766,110.998 158.242,112.522 158.242,119.634 152.908,124.968 152.908,135.89 153.289,136.271 v1(153.521,136.271) 153.804,136.271 153.985,136.09 172.451,136.09 172.905,135.636 173.425,135.636 v1(173.427,135.634)
CAN_TX: H14.23 U34.1 U41.26 | length 61.9
  Top Layer w0.2: U34.1@151.87,133.985 152.781,133.985 153.543,134.747 153.543,135.487 v1(153.521,135.509) ; v1(173.427,134.999) 175.078,133.348 U41.26@177.364,133.348
  Bottom Layer w0.2: H14.23@162.179,110.236 161.471,110.236 160.782,110.925 160.782,114.3 160.362,114.72 159.186,114.72 158.877,115.029 158.877,115.57 159.131,115.824 160.274,115.824 160.641,116.191 160.641,116.65 160.248,117.042 159.137,117.042 158.877,117.302 158.877,117.727 159.077,117.927 159.837,117.927 160.147,118.237 160.147,118.637 153.521,125.263 v1(153.521,135.509) 153.702,135.69 172.158,135.69 172.849,134.999 v1(173.427,134.999)
CP210-5V: C361.2 C362.2 D1.5 D8.2 U37.7 U37.8 | length 15.9
  Top Layer w0.312: D1.5@136.132,115.697 v1(136.894,115.697) ; U37.8@142.875,116.84 142.813,116.778 142.813,115.316 142.813,113.411 142.813,111.596 v1(143.157,111.252) D8.2@144.104,111.252
  Bottom Layer w0.312: v1(136.894,115.697) 139.319,115.697 142.845,112.171 142.845,111.564 v1(143.157,111.252)
DN: D1.3 H16.3 USB1.5 USB1.7 | length 18.9
  Top Layer w0.2: D1.3@134.632,115.197 134.624,115.189 v1(133.985,115.189) 133.973,115.177 133.973,114.461 134.251,114.183 USB1.5@134.251,113.373 134.251,112.7 134.5,112.451 135.028,112.451 135.251,112.674 USB1.7@135.251,113.373
  Bottom Layer w0.2: H16.3@125.476,117.221 125.476,116.425 125.95,115.951 126.283,115.951 126.644,116.312 126.998,116.312 127.36,115.951 128.778,115.951 129.267,116.44 129.267,117.791 129.567,118.091 129.85,118.091 130.023,117.918 130.233,117.918 130.406,118.091 130.702,118.091 131.105,117.688 131.105,117.194 131.416,116.883 131.91,116.883 132.156,116.637 132.156,115.571 132.538,115.189 v1(133.985,115.189)
DP: D1.1 H16.2 USB1.6 USB1.8 | length 18.9
  Top Layer w0.2: D1.1@134.632,116.197 v1(135.255,116.197) 135.255,114.302 135.253,114.3 ; USB1.6@134.751,113.373 134.751,114.05 135.001,114.3 135.253,114.3 ; USB1.8@135.751,113.373 135.763,113.385 135.763,114.046 135.509,114.3 135.253,114.3
  Bottom Layer w0.2: H16.2@122.936,117.221 124.206,118.491 130.868,118.491 133.162,116.197 v1(135.255,116.197)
